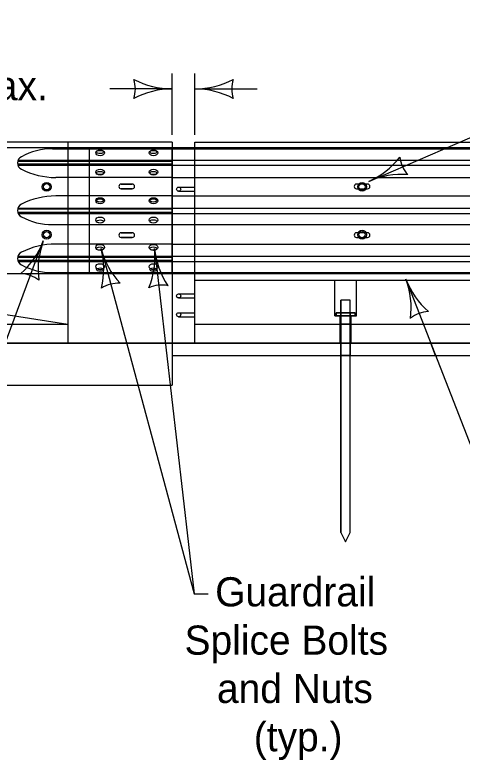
# Model space of a CAD drawing. Extents: x -2137026 to -2131464, y -2138478 to -2136524.
# Drawn here: x -2136774 to -2136540.6, y -2138332.4 to -2137943.6 of the extents above; entities that cross this region are included whole.
import ezdxf

# ---------------------------------------------------------------- set-up
doc = ezdxf.new("R2010")
doc.units = 0
for name, color, linetype in [('conPaving', 7, 'Continuous'), ('Level 2', 7, 'Continuous'), ('Level 3', 7, 'Continuous'), ('Level 41', 7, 'Continuous'), ('Level 9', 7, 'Continuous')]:
    doc.layers.add(name, color=color, linetype=linetype)

msp = doc.modelspace()

# ---------------------------------------------------------------- linework, layer by layer
at = {"layer": 'conPaving'}
for p, q in [((-2136691.89, -2138013.05), (-2136786.1, -2138013.05)), ((-2136493.65, -2138013.05), (-2136691.89, -2138013.05)), ((-2136718.52, -2138031.89), (-2136712.78, -2138031.89)), ((-2136712.78, -2138034.35), (-2136718.52, -2138034.35)), ((-2136718.52, -2138057.28), (-2136712.78, -2138057.28)), ((-2136712.78, -2138059.74), (-2136718.52, -2138059.74)), ((-2136786.1, -2138078.58), (-2136691.89, -2138078.58)), ((-2136691.89, -2138078.58), (-2136493.65, -2138078.58)), ((-2136691.53, -2138114.82), (-2136691.9, -2138114.82)), ((-2136691.9, -2138114.82), (-2136691.9, -2138121.37)), ((-2136603.84, -2138114.82), (-2136691.53, -2138114.82)), ((-2136603.84, -2138121.37), (-2136603.84, -2138114.82)), ((-2136598.55, -2138114.82), (-2136598.92, -2138114.82)), ((-2136598.92, -2138114.82), (-2136598.92, -2138121.37)), ((-2136556.91, -2138114.82), (-2136598.55, -2138114.82)), ((-2136556.91, -2138114.82), (-2136554.36, -2138121.37)), ((-2136554.36, -2138121.37), (-2136556.91, -2138114.82)), ((-2136691.9, -2138121.37), (-2136603.84, -2138121.37)), ((-2136598.92, -2138121.37), (-2136554.36, -2138121.37)), ((-2136554.36, -2138121.37), (-2136436.72, -2138121.37))]:
    msp.add_line(p, q, dxfattribs=at)
msp.add_lwpolyline([(-2136436.72, -2138114.82), (-2136437.09, -2138114.82), (-2136473.58, -2138114.82), (-2136512.9, -2138114.82), (-2136556.91, -2138114.82)], dxfattribs=at)
for centre, start, end in [((-2136718.52, -2138033.12), 90, 270), ((-2136712.78, -2138033.12), 270, 90), ((-2136718.52, -2138058.51), 90, 270), ((-2136712.78, -2138058.51), 270, 90)]:
    msp.add_arc(centre, 1.23, start, end, dxfattribs=at)
at = {"layer": 'Level 2'}
for p, q in [((-2136589.27, -2138030.55), (-2136388.5, -2137943.65)), ((-2136691.9, -2138006.29), (-2136691.9, -2137974.23)), ((-2136680.02, -2138006.29), (-2136680.02, -2137974.23)), ((-2136691.9, -2137982.26), (-2136724.47, -2137982.26)), ((-2136680.02, -2137982.26), (-2136647.45, -2137982.26)), ((-2136691.9, -2138009.96), (-2136940.96, -2138009.96)), ((-2136746.34, -2138009.96), (-2136746.34, -2138114.82)), ((-2136691.9, -2138009.96), (-2136691.9, -2138114.82)), ((-2136680.02, -2138114.57), (-2136680.02, -2138009.96)), ((-2136680.02, -2138009.96), (-2136188.5, -2138009.96)), ((-2136846.85, -2138296.37), (-2136759.19, -2138061.56)), ((-2136728.95, -2138065.54), (-2136680.42, -2138245.6)), ((-2136701.11, -2138065.53), (-2136680.42, -2138245.6)), ((-2136746.34, -2138105.06), (-2136940.96, -2138074.8)), ((-2136680.02, -2138082.05), (-2136188.5, -2138082.05)), ((-2136569.88, -2138081.45), (-2136489.13, -2138289.19)), ((-2136746.34, -2138105.06), (-2136940.96, -2138105.06)), ((-2136680.02, -2138104.99), (-2136188.5, -2138104.99)), ((-2136679.78, -2138114.82), (-2136512.9, -2138114.82)), ((-2136680.42, -2138245.6), (-2136673.13, -2138245.6))]:
    msp.add_line(p, q, dxfattribs=at)
for centre, radius, start, end in [((-2136727.54, -2137982.26), 16.42, 342.2667, 17.7334), ((-2136691.9, -2137939.76), 42.5, 241.9275, 270), ((-2136727.54, -2137982.26), 16.42, 342.2667, 17.7334), ((-2136691.9, -2137939.76), 42.5, 241.9275, 270), ((-2136680.02, -2137939.76), 42.5, 270, 298.0725), ((-2136680.02, -2137939.76), 42.5, 270, 298.0725), ((-2136644.39, -2137982.26), 16.42, 162.2666, 197.7334), ((-2136644.39, -2137982.26), 16.42, 162.2666, 197.7334), ((-2136691.9, -2138024.76), 42.5, 90, 118.0725), ((-2136691.9, -2138024.76), 42.5, 90, 118.0725), ((-2136680.02, -2138024.76), 42.5, 61.9275, 90), ((-2136680.02, -2138024.76), 42.5, 61.9275, 90), ((-2136606.59, -2137991.74), 42.5, 294.0555, 322.128), ((-2136556.72, -2138016.03), 16.42, 186.3222, 221.7889), ((-2136571.94, -2138069.36), 42.5, 85.9831, 114.0555), ((-2136799, -2138046.7), 42.5, 311.4536, 339.5261), ((-2136719.37, -2138076.43), 42.5, 159.5261, 187.5985), ((-2136770.11, -2138076.13), 42.5, 346.3629, 14.4353), ((-2136687.79, -2138054.95), 42.5, 194.4353, 222.5078), ((-2136743.39, -2138069.91), 42.5, 337.8338, 5.9063), ((-2136658.84, -2138061.16), 42.5, 185.9063, 213.9788), ((-2136771.65, -2138094.95), 16.42, 51.7927, 87.2594), ((-2136609.66, -2138096.4), 42.5, 352.5207, 20.5932), ((-2136530.09, -2138066.51), 42.5, 200.5932, 228.6657), ((-2136720.07, -2138100.05), 16.42, 86.702, 122.1687), ((-2136697.44, -2138100.98), 16.42, 78.173, 113.6397), ((-2136557.34, -2138114.81), 16.42, 92.8599, 128.3266)]:
    msp.add_arc(centre, radius, start, end, dxfattribs=at)
at = {"layer": 'Level 3'}
msp.add_line((-2136691.93, -2138114.82), (-2136940.96, -2138114.82), dxfattribs=at)
at = {"layer": 'Level 41'}
for p, q in [((-2136688.52, -2138033.48), (-2136680.02, -2138033.48)), ((-2136688.52, -2138035.6), (-2136680.02, -2138035.6)), ((-2136607.04, -2138100.62), (-2136607.04, -2138082.05)), ((-2136595.72, -2138100.62), (-2136595.72, -2138082.05)), ((-2136688.52, -2138089.18), (-2136680.03, -2138089.18)), ((-2136688.52, -2138091.31), (-2136680.03, -2138091.31)), ((-2136688.52, -2138099.01), (-2136680.03, -2138099.01)), ((-2136688.52, -2138101.14), (-2136680.03, -2138101.14)), ((-2136607.04, -2138100.62), (-2136595.72, -2138100.62)), ((-2136604.21, -2138114.82), (-2136604.21, -2138100.62)), ((-2136598.55, -2138114.82), (-2136598.55, -2138100.62))]:
    msp.add_line(p, q, dxfattribs=at)
for centre in [(-2136688.52, -2138034.54), (-2136688.52, -2138090.24), (-2136688.52, -2138100.07)]:
    msp.add_circle(centre, 1.06, dxfattribs=at)
at = {"layer": 'Level 9'}
for p, q in [((-2136691.89, -2138013.05), (-2136786.1, -2138013.05)), ((-2136691.89, -2138013.05), (-2136786.1, -2138013.05)), ((-2136735.31, -2138013.05), (-2136735.31, -2138078.58)), ((-2136691.89, -2138078.58), (-2136691.89, -2138013.05)), ((-2136772.58, -2138019.96), (-2136691.89, -2138019.96)), ((-2136772.36, -2138019.35), (-2136691.89, -2138019.35)), ((-2136691.89, -2138021.5), (-2136772.66, -2138021.5)), ((-2136772.49, -2138022.11), (-2136691.89, -2138022.11)), ((-2136691.89, -2138045.05), (-2136772.66, -2138045.05)), ((-2136772.58, -2138046.58), (-2136691.89, -2138046.58)), ((-2136772.49, -2138044.43), (-2136691.89, -2138044.43)), ((-2136772.36, -2138047.19), (-2136691.89, -2138047.19)), ((-2136691.89, -2138070.13), (-2136772.66, -2138070.13)), ((-2136772.49, -2138069.52), (-2136691.89, -2138069.52)), ((-2136772.58, -2138071.67), (-2136691.89, -2138071.67)), ((-2136772.36, -2138072.28), (-2136691.89, -2138072.28)), ((-2136786.1, -2138078.58), (-2136691.89, -2138078.58)), ((-2136786.1, -2138078.58), (-2136691.89, -2138078.58)), ((-2136691.89, -2138078.58), (-2136493.65, -2138078.58)), ((-2136691.89, -2138078.58), (-2136493.65, -2138078.58)), ((-2136598.92, -2138092.42), (-2136603.84, -2138092.42)), ((-2136603.84, -2138092.42), (-2136603.84, -2138098.98)), ((-2136598.92, -2138092.42), (-2136603.84, -2138092.42)), ((-2136603.84, -2138213.67), (-2136603.84, -2138092.42)), ((-2136598.92, -2138098.98), (-2136598.92, -2138092.42)), ((-2136598.92, -2138213.67), (-2136598.92, -2138092.42)), ((-2136606.29, -2138098.98), (-2136606.29, -2138100.62)), ((-2136603.84, -2138098.98), (-2136606.29, -2138098.98)), ((-2136606.29, -2138100.62), (-2136606.29, -2138098.98)), ((-2136606.29, -2138100.62), (-2136604.21, -2138100.62)), ((-2136604.21, -2138100.62), (-2136603.84, -2138100.62)), ((-2136598.92, -2138098.98), (-2136603.84, -2138098.98)), ((-2136603.84, -2138098.98), (-2136603.84, -2138100.62)), ((-2136603.84, -2138100.62), (-2136603.84, -2138098.98)), ((-2136603.84, -2138098.98), (-2136598.92, -2138098.98)), ((-2136598.92, -2138100.62), (-2136603.84, -2138100.62)), ((-2136603.84, -2138100.62), (-2136603.84, -2138104.99)), ((-2136603.84, -2138100.62), (-2136598.92, -2138100.62)), ((-2136598.92, -2138100.62), (-2136598.92, -2138098.98)), ((-2136598.92, -2138098.98), (-2136598.92, -2138100.62)), ((-2136598.92, -2138104.99), (-2136598.92, -2138100.62)), ((-2136598.92, -2138104.99), (-2136603.84, -2138104.99)), ((-2136603.84, -2138104.99), (-2136603.84, -2138114.82)), ((-2136603.84, -2138104.99), (-2136598.92, -2138104.99)), ((-2136598.92, -2138114.82), (-2136598.92, -2138104.99)), ((-2136987.54, -2138114.82), (-2134196.38, -2138114.82)), ((-2136691.9, -2138114.82), (-2136691.9, -2138121.37)), ((-2136691.9, -2138114.82), (-2136691.9, -2138136.77)), ((-2136680.02, -2138114.57), (-2136679.78, -2138114.82)), ((-2136598.92, -2138114.82), (-2136603.84, -2138114.82)), ((-2136603.84, -2138114.82), (-2136603.84, -2138121.37)), ((-2136603.84, -2138114.82), (-2136598.92, -2138114.82)), ((-2136598.92, -2138121.37), (-2136598.92, -2138114.82)), ((-2136691.9, -2138121.37), (-2134672.37, -2138121.37)), ((-2136598.92, -2138121.37), (-2136603.84, -2138121.37)), ((-2136603.84, -2138121.37), (-2136603.84, -2138213.67)), ((-2136603.84, -2138121.37), (-2136598.92, -2138121.37)), ((-2136598.92, -2138213.67), (-2136598.92, -2138121.37)), ((-2136998.61, -2138136.77), (-2136691.9, -2138136.77)), ((-2136603.84, -2138213.67), (-2136601.38, -2138218.58)), ((-2136603.84, -2138213.67), (-2136601.38, -2138218.58)), ((-2136601.38, -2138218.58), (-2136598.92, -2138213.67)), ((-2136601.38, -2138218.58), (-2136598.92, -2138213.67))]:
    msp.add_line(p, q, dxfattribs=at)
for points in [[(-2136754.3, -2138013.54), (-2136691.89, -2138013.54)], [(-2136691.89, -2138013.05), (-2136493.65, -2138013.05)], [(-2136691.89, -2138013.54), (-2136493.65, -2138013.54)], [(-2136691.89, -2138019.35), (-2136493.65, -2138019.35)], [(-2136691.89, -2138022.11), (-2136493.65, -2138022.11)], [(-2136691.89, -2138028.46), (-2136752.67, -2138028.46)], [(-2136712.78, -2138031.89), (-2136718.52, -2138031.89)], [(-2136712.78, -2138031.89), (-2136718.52, -2138031.89)], [(-2136691.89, -2138028.46), (-2136493.65, -2138028.46)], [(-2136589.9, -2138031.89), (-2136595.64, -2138031.89)], [(-2136589.9, -2138031.89), (-2136595.64, -2138031.89)], [(-2136718.52, -2138034.35), (-2136712.78, -2138034.35)], [(-2136718.52, -2138034.35), (-2136712.78, -2138034.35)], [(-2136595.64, -2138034.35), (-2136589.9, -2138034.35)], [(-2136595.64, -2138034.35), (-2136589.9, -2138034.35)], [(-2136691.89, -2138038.08), (-2136752.67, -2138038.08)], [(-2136691.89, -2138038.08), (-2136493.65, -2138038.08)], [(-2136691.89, -2138044.43), (-2136493.65, -2138044.43)], [(-2136691.89, -2138047.19), (-2136493.65, -2138047.19)], [(-2136754.3, -2138053), (-2136691.89, -2138053)], [(-2136691.89, -2138053), (-2136493.65, -2138053)], [(-2136712.78, -2138057.28), (-2136718.52, -2138057.28)], [(-2136712.78, -2138057.28), (-2136718.52, -2138057.28)], [(-2136589.9, -2138057.28), (-2136595.64, -2138057.28)], [(-2136589.9, -2138057.28), (-2136595.64, -2138057.28)], [(-2136691.89, -2138063.17), (-2136752.67, -2138063.17)], [(-2136718.52, -2138059.74), (-2136712.78, -2138059.74)], [(-2136718.52, -2138059.74), (-2136712.78, -2138059.74)], [(-2136691.89, -2138063.17), (-2136493.65, -2138063.17)], [(-2136595.64, -2138059.74), (-2136589.9, -2138059.74)], [(-2136595.64, -2138059.74), (-2136589.9, -2138059.74)], [(-2136691.89, -2138069.52), (-2136493.65, -2138069.52)], [(-2136691.89, -2138072.28), (-2136493.65, -2138072.28)], [(-2136754.3, -2138078.09), (-2136691.89, -2138078.09)], [(-2136691.89, -2138078.09), (-2136493.65, -2138078.09)], [(-2136606.29, -2138098.98), (-2136596.46, -2138098.98), (-2136596.46, -2138100.62), (-2136606.29, -2138100.62)], [(-2136596.46, -2138100.62), (-2136596.46, -2138098.98), (-2136598.92, -2138098.98)], [(-2136598.92, -2138100.62), (-2136598.55, -2138100.62), (-2136596.46, -2138100.62)]]:
    msp.add_lwpolyline(points, dxfattribs=at)
for centre, radius in [((-2136757.43, -2138033.32), 2.3), ((-2136757.43, -2138033.32), 1.64), ((-2136757.43, -2138033.32), 1.64), ((-2136592.77, -2138033.32), 2.3), ((-2136592.77, -2138033.32), 1.64), ((-2136592.77, -2138033.32), 1.64), ((-2136757.43, -2138058.31), 2.3), ((-2136757.43, -2138058.31), 1.64), ((-2136757.43, -2138058.31), 1.64), ((-2136592.77, -2138058.31), 2.3), ((-2136592.77, -2138058.31), 1.64), ((-2136592.77, -2138058.31), 1.64)]:
    msp.add_circle(centre, radius, dxfattribs=at)
for centre, radius, start, end in [((-2136754.77, -2138046.25), 32.71, 89.1823, 118.8905), ((-2136769.12, -2138020.89), 3.59, 113.8801, 246.1199), ((-2136752.71, -2137989.09), 39.37, 243.015, 270.056), ((-2136718.52, -2138033.12), 1.23, 90, 270), ((-2136718.52, -2138033.12), 1.23, 90, 270), ((-2136712.78, -2138033.12), 1.23, 270, 90), ((-2136712.78, -2138033.12), 1.23, 270, 90), ((-2136595.64, -2138033.12), 1.23, 90, 270), ((-2136595.64, -2138033.12), 1.23, 90, 270), ((-2136589.9, -2138033.12), 1.23, 270, 90), ((-2136589.9, -2138033.12), 1.23, 270, 90), ((-2136752.71, -2138077.46), 39.37, 89.944, 116.985), ((-2136769.12, -2138045.65), 3.59, 113.8801, 246.1199), ((-2136754.77, -2138020.3), 32.71, 241.1095, 270.8177), ((-2136718.52, -2138058.51), 1.23, 90, 270), ((-2136718.52, -2138058.51), 1.23, 90, 270), ((-2136712.78, -2138058.51), 1.23, 270, 90), ((-2136712.78, -2138058.51), 1.23, 270, 90), ((-2136595.64, -2138058.51), 1.23, 90, 270), ((-2136595.64, -2138058.51), 1.23, 90, 270), ((-2136589.9, -2138058.51), 1.23, 270, 90), ((-2136589.9, -2138058.51), 1.23, 270, 90), ((-2136752.71, -2138102.54), 39.37, 89.944, 116.985), ((-2136769.12, -2138070.74), 3.59, 113.8801, 246.1199), ((-2136754.77, -2138045.38), 32.71, 241.1095, 270.8177)]:
    msp.add_arc(centre, radius, start, end, dxfattribs=at)
for centre, major_axis, ratio in [((-2136729.55, -2138015.57), (-2.26, 0), 0.685714), ((-2136729.56, -2138015.14), (-1.84, 0), 0.456281), ((-2136701.68, -2138015.57), (-2.26, 0), 0.685714), ((-2136701.72, -2138015.15), (-1.84, 0), 0.456281), ((-2136729.55, -2138025.67), (-2.26, 0), 0.685714), ((-2136701.68, -2138025.67), (-2.26, 0), 0.685714), ((-2136729.58, -2138026.09), (-1.84, 0), 0.456281), ((-2136701.74, -2138026.1), (-1.84, 0), 0.456281), ((-2136729.55, -2138040.57), (-2.26, 0), 0.685714), ((-2136729.58, -2138040.45), (-1.84, 0), 0.456281), ((-2136701.68, -2138040.57), (-2.26, 0), 0.685714), ((-2136701.74, -2138040.45), (-1.84, 0), 0.456281), ((-2136729.55, -2138050.66), (-2.26, 0), 0.685714), ((-2136729.56, -2138051.41), (-1.84, 0), 0.456281), ((-2136701.68, -2138050.66), (-2.26, 0), 0.685714), ((-2136701.72, -2138051.4), (-1.84, 0), 0.456281), ((-2136729.55, -2138064.91), (-2.26, 0), 0.685714), ((-2136729.58, -2138065.54), (-1.84, 0), 0.456281), ((-2136701.68, -2138064.91), (-2.26, 0), 0.685714), ((-2136701.74, -2138065.53), (-1.84, 0), 0.456281), ((-2136729.55, -2138075), (-2.26, 0), 0.685714), ((-2136701.68, -2138075), (-2.26, 0), 0.685714), ((-2136729.56, -2138076.49), (-1.84, 0), 0.456281), ((-2136701.72, -2138076.48), (-1.84, 0), 0.456281)]:
    msp.add_ellipse(centre, major_axis=major_axis, ratio=ratio, dxfattribs=at)

# ---------------------------------------------------------------- texts
at = {"layer": 'Level 3'}
for s, p in [('4" min., 12" max.', (-2136910.21, -2137988.16)), ('Guardrail', (-2136669.46, -2138252.19)), ('Splice Bolts', (-2136685.43, -2138277.39)), ('and Nuts', (-2136668.52, -2138302.59)), ('(typ.)', (-2136649.29, -2138327.79))]:
    msp.add_text(s, height=15.2, dxfattribs=at).set_placement(p)

doc.saveas('drawing.dxf')
